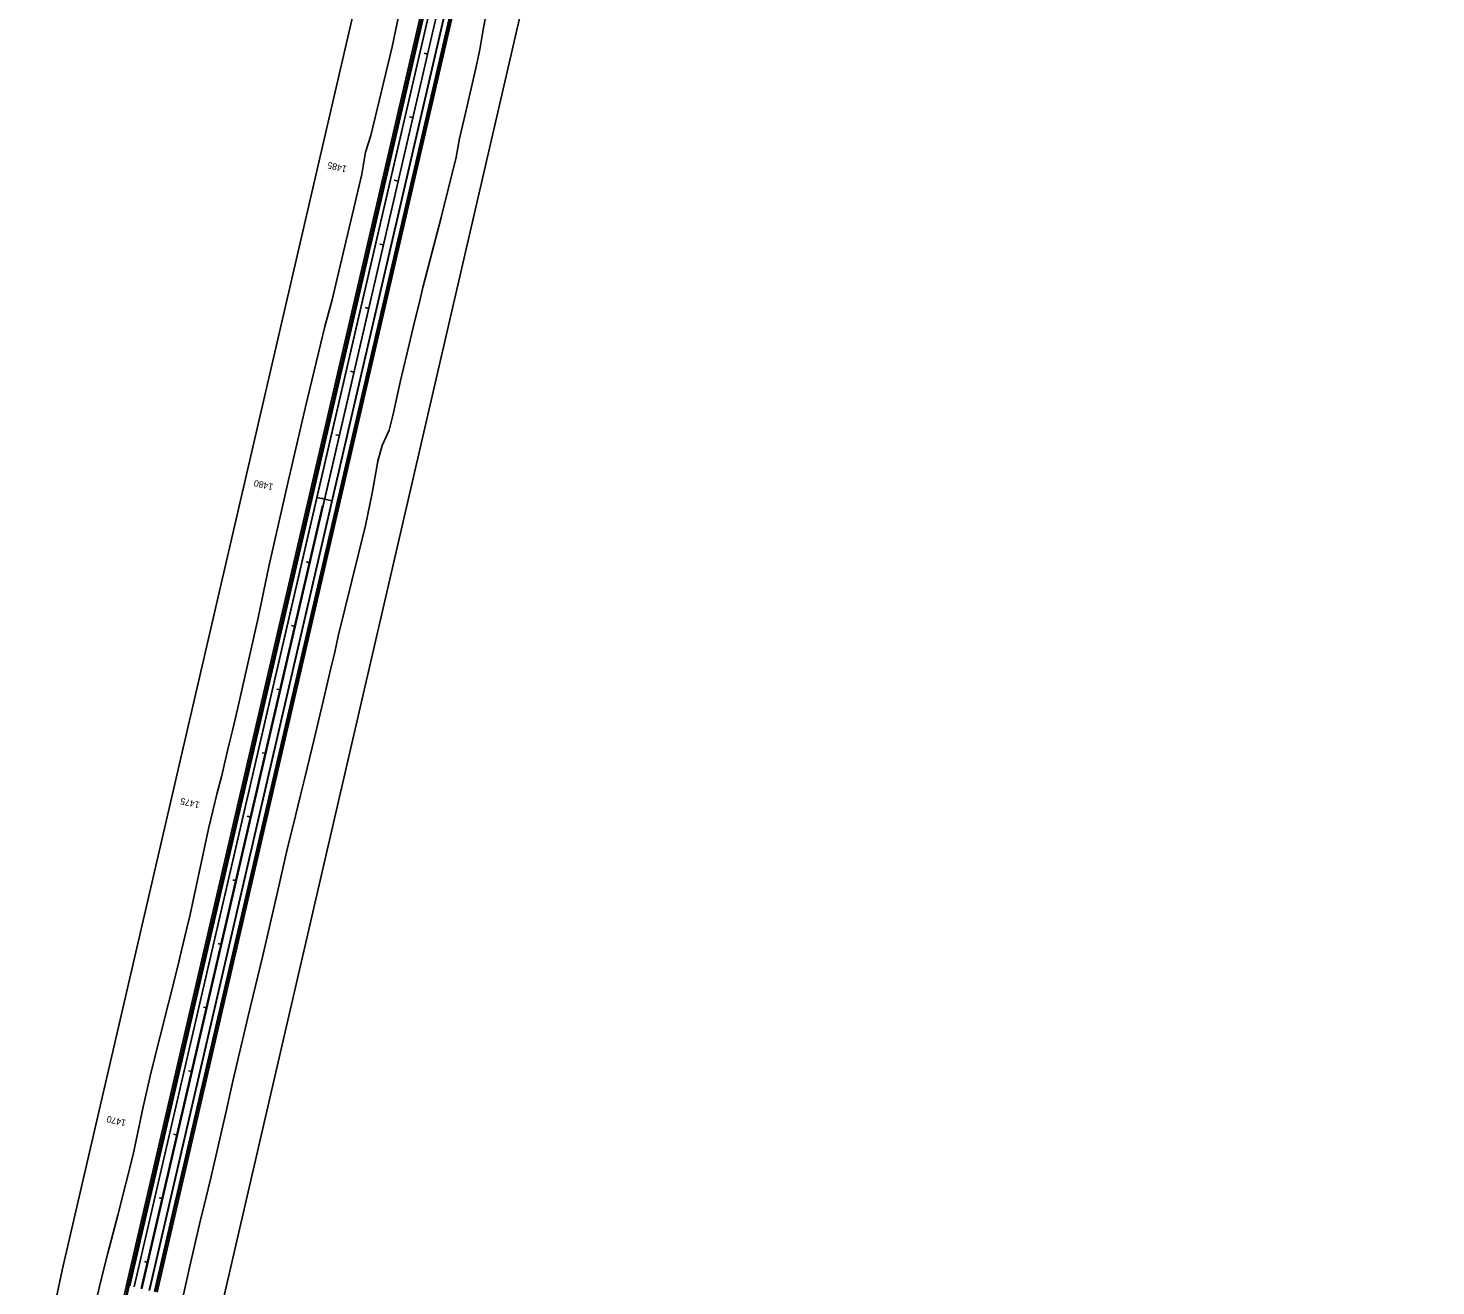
# Model space of a CAD drawing. Extents: x 21596487 to 21601936, y 8263704 to 8275922.
# Drawn here: x 21596555 to 21598711, y 8267207 to 8269134 of the extents above; entities that cross this region are included whole.
import ezdxf

# ---------------------------------------------------------------- set-up
doc = ezdxf.new("R2010")
doc.units = 0
for name, color, linetype in [('Default', 7, 'Continuous'), ('dsnGroundLineIntercept', 7, 'Continuous'), ('dsnPaintPlaceBrokenCenterLineYellow', 7, 'Continuous'), ('dsnPaintPlaceDottedLineYellow', 7, 'Continuous'), ('dsnPaintPlaceEdgeLineLeftYellow', 7, 'Continuous'), ('dsnXsROWLabelLineExist', 7, 'Continuous'), ('EdgeUnpaved', 7, 'Continuous'), ('ErosionControl', 7, 'Continuous'), ('Joints', 7, 'Continuous'), ('TC_DNC', 7, 'Continuous'), ('TC_GranularBackFill', 7, 'Continuous'), ('TC_MacadamStone', 7, 'Continuous'), ('TC_SpecialBackfill', 7, 'Continuous'), ('Wall', 7, 'Continuous')]:
    doc.layers.add(name, color=color, linetype=linetype)

msp = doc.modelspace()

# ---------------------------------------------------------------- linework, layer by layer
at = {"layer": 'Default'}
msp.add_line((21596728.7, 8267202.6), (21598588.8, 8275242.6), dxfattribs=at)
msp.add_line((21596728.7, 8267202.6), (21598588.8, 8275242.6), dxfattribs=at)
at = {"layer": 'dsnGroundLineIntercept'}
for points in [[(21597144, 8269259.8), (21597112, 8269105), (21597079.4, 8268969.2), (21597071.4, 8268943.9), (21597065.5, 8268909.8), (21597055.4, 8268866.6), (21597025.8, 8268741.6), (21597020, 8268717.3), (21597008.9, 8268676.4), (21596979.4, 8268553.4), (21596952.8, 8268439.2), (21596923, 8268308.9), (21596906.9, 8268230.3), (21596879.3, 8268108.4), (21596873.5, 8268084), (21596867.8, 8268059.7), (21596862.1, 8268035.4), (21596856.5, 8268011), (21596850.8, 8267986.6), (21596844, 8267962.3), (21596830.8, 8267906.9), (21596802.5, 8267775.7), (21596797.8, 8267754.8), (21596788.8, 8267718.7), (21596783.2, 8267694.4), (21596742.3, 8267532.7), (21596730.6, 8267481.2), (21596715.2, 8267408), (21596691.8, 8267315.2), (21596676.5, 8267257.2), (21596664.5, 8267208.3), (21596658.6, 8267183.2)], [(21596783.1, 8267152.4), (21596800.6, 8267230.5), (21596818.6, 8267308), (21596822.9, 8267325.9), (21596835, 8267374.4), (21596857.1, 8267472), (21596868.2, 8267520.7), (21596890.9, 8267618.1), (21596914.4, 8267715.3), (21596937.4, 8267814.5), (21596951.9, 8267877.9), (21596959.8, 8267910.1), (21596971.7, 8267958.7), (21596977.7, 8267982.9), (21596989.5, 8268031.5), (21597006.8, 8268104.5), (21597018.2, 8268153.2), (21597024.2, 8268177.5), (21597029.3, 8268202), (21597071.1, 8268371.9), (21597081.7, 8268421.2), (21597090.1, 8268470.2), (21597096.8, 8268494.1), (21597107.3, 8268517.8), (21597113.4, 8268542.5), (21597124.2, 8268591.3), (21597147.4, 8268687.8), (21597153.4, 8268712.1), (21597159.3, 8268736.4), (21597187.3, 8268843.8), (21597210.1, 8268936.1), (21597215, 8268964.4), (21597224.3, 8269003.6), (21597240.1, 8269072.5), (21597246.2, 8269101.2), (21597250.4, 8269125.3), (21597259.5, 8269175.6)]]:
    msp.add_lwpolyline(points, dxfattribs=at)
at = {"layer": 'dsnPaintPlaceBrokenCenterLineYellow'}
for p, q in [((21597006.2, 8268402), (21598343, 8274180.5)), ((21596728.7, 8267202.6), (21597006.2, 8268402))]:
    msp.add_line(p, q, dxfattribs=at)
at = {"layer": 'dsnPaintPlaceDottedLineYellow'}
for p, q in [((21596717, 8267205.3), (21598523, 8275011.8)), ((21596739.7, 8267200), (21598545.7, 8275006.6))]:
    msp.add_line(p, q, dxfattribs=at)
at = {"layer": 'dsnPaintPlaceEdgeLineLeftYellow'}
msp.add_line((21596727.8, 8267202.8), (21597005.3, 8268402.2), dxfattribs=at)
at = {"layer": 'dsnXsROWLabelLineExist'}
for p, q in [((21596850.5, 8267174.4), (21598710.5, 8275214.5)), ((21596606.9, 8267230.7), (21597486.5, 8271032.9))]:
    msp.add_line(p, q, dxfattribs=at)
msp.add_arc((21598589.4, 8266772.1), 2034.9, 166.974, 199.9238, dxfattribs=at)
at = {"layer": 'EdgeUnpaved'}
for p, q in [((21596709.9, 8267206.9), (21598472.3, 8274824.9)), ((21596710.4, 8267206.8), (21598472.9, 8274825.4))]:
    msp.add_line(p, q, dxfattribs=at)
at = {"layer": 'ErosionControl'}
for p, q in [((21597166.3, 8269094), (21597160.9, 8269095.3)), ((21597143.8, 8268996.6), (21597138.4, 8268997.8)), ((21597121.2, 8268899.2), (21597115.3, 8268900.6)), ((21597098.7, 8268801.7), (21597093.3, 8268803)), ((21597076.1, 8268704.3), (21597070.8, 8268705.6)), ((21597053.6, 8268606.9), (21597048.2, 8268608.1)), ((21597031.1, 8268509.5), (21597025.7, 8268510.7)), ((21597008.5, 8268412), (21597002.6, 8268413.4)), ((21596986, 8268314.6), (21596980.6, 8268315.9)), ((21596963.4, 8268217.2), (21596958.1, 8268218.4)), ((21596940.9, 8268119.8), (21596935.6, 8268121)), ((21596918.4, 8268022.3), (21596913, 8268023.6)), ((21596895.8, 8267924.9), (21596889.9, 8267926.3)), ((21596873.3, 8267827.5), (21596867.9, 8267828.7)), ((21596850.8, 8267730.1), (21596845.4, 8267731.3)), ((21596828.2, 8267632.6), (21596822.9, 8267633.9)), ((21596805.7, 8267535.2), (21596800.3, 8267536.4)), ((21596783.1, 8267437.8), (21596777.2, 8267439.2)), ((21596760.6, 8267340.3), (21596755.2, 8267341.6)), ((21596738.1, 8267242.9), (21596732.7, 8267244.2))]:
    msp.add_line(p, q, dxfattribs=at)
at = {"layer": 'TC_DNC'}
for p, q in [((21596708, 8267207.3), (21598514, 8275013.9)), ((21596749.4, 8267197.8), (21598555.4, 8275004.4))]:
    msp.add_line(p, q, dxfattribs=at)
msp.add_arc((21598589.4, 8266772.1), 1931.1, 166.974, 199.9238, dxfattribs=at)
at = {"layer": 'TC_GranularBackFill'}
msp.add_line((21596728.7, 8267202.6), (21598588.8, 8275242.6), dxfattribs=at)
at = {"layer": 'TC_MacadamStone'}
for p, q in [((21596709.2, 8267207.1), (21598515.3, 8275013.6)), ((21596748.2, 8267198.1), (21598554.2, 8275004.6))]:
    msp.add_line(p, q, dxfattribs=at)
msp.add_arc((21598589.4, 8266772.1), 1929.9, 166.974, 199.9238, dxfattribs=at)
at = {"layer": 'TC_SpecialBackfill'}
for p, q in [((21597334.9, 8269876.1), (21596996.8, 8268414.7)), ((21597020.2, 8268409.3), (21597358.3, 8269870.7)), ((21596717, 8267205.3), (21596996.8, 8268414.7)), ((21597020.2, 8268409.3), (21596740.4, 8267199.9)), ((21596996.8, 8268414.7), (21597020.2, 8268409.3)), ((21596996.8, 8268414.7), (21597020.2, 8268409.3))]:
    msp.add_line(p, q, dxfattribs=at)
at = {"layer": 'Wall'}
for p, q in [((21596705.3, 8267208), (21598511.4, 8275014.5)), ((21596752.1, 8267197.2), (21598558.1, 8275003.7))]:
    msp.add_line(p, q, dxfattribs=at)
msp.add_arc((21598589.4, 8266772.1), 1933.9, 166.974, 199.9238, dxfattribs=at)

# ---------------------------------------------------------------- texts
at = {"layer": 'Joints'}
for s, p in [('1485', (21597043.3, 8268922.3)), ('1480', (21596930.6, 8268435.2)), ('1475', (21596817.9, 8267948.1)), ('1470', (21596705.2, 8267460.9))]:
    msp.add_text(s, height=10, rotation=166.974, dxfattribs=at).set_placement(p)

doc.saveas('drawing.dxf')
